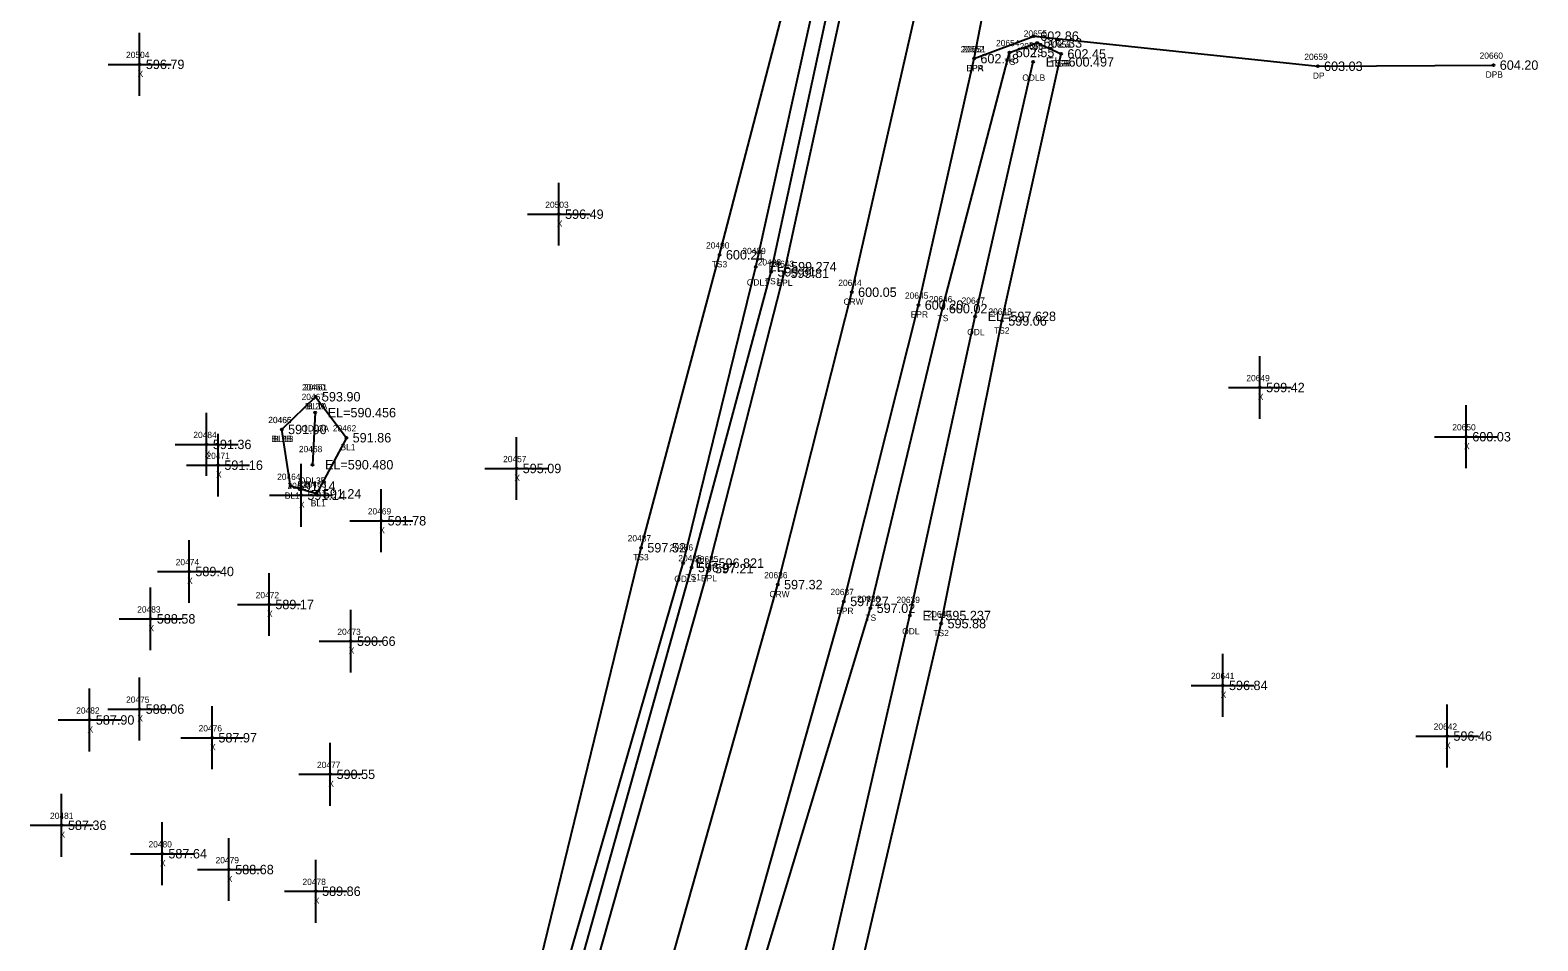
# Model space of a CAD drawing. Extents: x 1695443 to 1696344, y 1087542 to 1090645.
# Drawn here: x 1695668.2 to 1695908, y 1089671.2 to 1089816.1 of the extents above; entities that cross this region are included whole.
import ezdxf

# ---------------------------------------------------------------- set-up
doc = ezdxf.new("R2010")
doc.units = 0
for name, color, linetype in [('RD_DTM_BkLn1', 7, 'Continuous'), ('RD_DTM_BkLn2', 7, 'Continuous'), ('RD_DTM_BkLn_txCode', 7, 'Continuous'), ('RD_EX_Driveway', 7, 'Continuous'), ('RD_EX_Driveway_txCode', 7, 'Continuous'), ('RD_EX_H2O', 7, 'Continuous'), ('RD_EX_H2O_txCode', 7, 'Continuous'), ('RD_EX_Misc', 7, 'Continuous'), ('RD_EX_Misc_txCode', 7, 'Continuous'), ('RD_EX_Road', 7, 'Continuous'), ('RD_EX_Road_txCode', 7, 'Continuous'), ('RD_EX_TX_Driveway_ELEV', 7, 'Continuous'), ('RD_EX_TX_H2O_ELEV', 7, 'Continuous'), ('RD_EX_TX_Misc_ELEV', 7, 'Continuous'), ('RD_EX_TX_Road_ELEV', 7, 'Continuous'), ('RD_HC_Survey_ELEV', 7, 'Continuous'), ('RD_HC_Survey_txCode', 7, 'Continuous'), ('RD_SMD_Locator', 7, 'Continuous')]:
    doc.layers.add(name, color=color, linetype=linetype)

msp = doc.modelspace()

# ---------------------------------------------------------------- linework, layer by layer
at = {"layer": 'RD_DTM_BkLn1'}
msp.add_line((1695713.6, 1089757.78), (1695708.22, 1089752.58), dxfattribs=at)
for points in [[(1695813.78, 1089148.1), (1695785.55, 1089189.03), (1695758.89, 1089235.87), (1695740.64, 1089279.02), (1695725.17, 1089334.02), (1695718.27, 1089382.65), (1695717.41, 1089435.13), (1695722.03, 1089482.62), (1695732.64, 1089534.75), (1695759.85, 1089631.43), (1695787.11, 1089727.89), (1695798.89, 1089774.41), (1695810.31, 1089824.5), (1695818.49, 1089870.61), (1695825.85, 1089922.33), (1695831.69, 1089976.57), (1695835.49, 1090019.27), (1695844.06, 1090117.91), (1695852.56, 1090215.73), (1695861.78, 1090313.02), (1695870.8, 1090411.68), (1695879.44, 1090510.15), (1695888.04, 1090606.94)], [(1695713.6, 1089757.78), (1695718.49, 1089751.26), (1695713.75, 1089742.33), (1695709.63, 1089743.55), (1695708.22, 1089752.58)]]:
    msp.add_lwpolyline(points, dxfattribs=at)
at = {"layer": 'RD_DTM_BkLn2'}
for points in [[(1695696.87, 1089328.65), (1695685.13, 1089358.98), (1695692.41, 1089382.13), (1695691.76, 1089435.56), (1695699.73, 1089488.72), (1695712.17, 1089543.62), (1695742.06, 1089638.06), (1695765.36, 1089733.76), (1695777.86, 1089780.36), (1695790.39, 1089828.61), (1695799.49, 1089874.59), (1695809.45, 1089923.14)], [(1695802.49, 1089139.56), (1695797.31, 1089139.87), (1695796.55, 1089145.92), (1695767.85, 1089172.77), (1695752.08, 1089198.99), (1695743.04, 1089224.25), (1695723.93, 1089271.63), (1695706.46, 1089330), (1695701.78, 1089380.95), (1695703.12, 1089435.75), (1695708.88, 1089486.48), (1695720.72, 1089539.1), (1695747.1, 1089636.56), (1695773.41, 1089730.59), (1695786.04, 1089777.66), (1695796.55, 1089826.24), (1695804.53, 1089873.75), (1695809.45, 1089923.14)], [(1695824.1, 1089156.08), (1695822.08, 1089163.12), (1695799.61, 1089199.21), (1695776.92, 1089245.16), (1695754.8, 1089284.38), (1695737.73, 1089336.15), (1695730.34, 1089383.59), (1695730.57, 1089435.13), (1695734.2, 1089480.03), (1695745.77, 1089531.16), (1695772.55, 1089627.13), (1695801.84, 1089724.13), (1695813.32, 1089771.8), (1695823.97, 1089812.55), (1695828.38, 1089814.06), (1695832.18, 1089812.32)], [(1695733.01, 1089422.34), (1695739.17, 1089435.08), (1695740.22, 1089478.28), (1695758.62, 1089527.7), (1695775.29, 1089579.66), (1695790.54, 1089625.04), (1695813.11, 1089721.69), (1695822.77, 1089769.83), (1695832.18, 1089812.32)]]:
    msp.add_lwpolyline(points, dxfattribs=at)
at = {"layer": 'RD_EX_Driveway'}
msp.add_lwpolyline([(1695818.34, 1089811.57), (1695827.86, 1089815.15), (1695873, 1089810.36), (1695900.95, 1089810.54)], dxfattribs=at)
at = {"layer": 'RD_EX_H2O'}
msp.add_line((1695713.52, 1089755.25), (1695713.09, 1089746.96), dxfattribs=at)
for points in [[(1695696.87, 1089328.65), (1695699.57, 1089380.43), (1695700.06, 1089435.96), (1695707.01, 1089487.43), (1695718.96, 1089539.87), (1695744.93, 1089637.33), (1695772.06, 1089731.31), (1695783.6, 1089778.47), (1695794.38, 1089827.05), (1695802.7, 1089874.04), (1695809.45, 1089923.14)], [(1695733.01, 1089422.34), (1695733.36, 1089435.29), (1695736.08, 1089479.97), (1695750.56, 1089529.82), (1695767.47, 1089581.7), (1695784.92, 1089622.19), (1695808.14, 1089722.97), (1695818.49, 1089770.57), (1695827.73, 1089811.05)]]:
    msp.add_lwpolyline(points, dxfattribs=at)
at = {"layer": 'RD_EX_Misc'}
for p, q in [((1695685.6, 1089805.66), (1695685.6, 1089815.66)), ((1695680.6, 1089810.66), (1695690.6, 1089810.66)), ((1695752.28, 1089781.82), (1695752.28, 1089791.82)), ((1695747.28, 1089786.82), (1695757.28, 1089786.82)), ((1695863.79, 1089754.25), (1695863.79, 1089764.25)), ((1695858.79, 1089759.25), (1695868.79, 1089759.25)), ((1695696.26, 1089745.2), (1695696.26, 1089755.2)), ((1695896.58, 1089746.42), (1695896.58, 1089756.42)), ((1695691.26, 1089750.2), (1695701.26, 1089750.2)), ((1695698.08, 1089741.89), (1695698.08, 1089751.89)), ((1695745.54, 1089741.37), (1695745.54, 1089751.37)), ((1695891.58, 1089751.42), (1695901.58, 1089751.42)), ((1695711.28, 1089737.11), (1695711.28, 1089747.11)), ((1695693.08, 1089746.89), (1695703.08, 1089746.89)), ((1695740.54, 1089746.37), (1695750.54, 1089746.37)), ((1695724.05, 1089733.05), (1695724.05, 1089743.05)), ((1695706.28, 1089742.11), (1695716.28, 1089742.11)), ((1695719.05, 1089738.05), (1695729.05, 1089738.05)), ((1695693.47, 1089724.98), (1695693.47, 1089734.98)), ((1695688.47, 1089729.98), (1695698.47, 1089729.98)), ((1695706.19, 1089719.73), (1695706.19, 1089729.73)), ((1695687.34, 1089717.44), (1695687.34, 1089727.44)), ((1695701.19, 1089724.73), (1695711.19, 1089724.73)), ((1695719.18, 1089713.89), (1695719.18, 1089723.89)), ((1695682.34, 1089722.44), (1695692.34, 1089722.44)), ((1695714.18, 1089718.89), (1695724.18, 1089718.89)), ((1695857.88, 1089706.86), (1695857.88, 1089716.86)), ((1695677.64, 1089701.36), (1695677.64, 1089711.36)), ((1695685.57, 1089703.09), (1695685.57, 1089713.09)), ((1695852.88, 1089711.86), (1695862.88, 1089711.86)), ((1695893.58, 1089698.8), (1695893.58, 1089708.8)), ((1695672.64, 1089706.36), (1695682.64, 1089706.36)), ((1695680.57, 1089708.09), (1695690.57, 1089708.09)), ((1695697.14, 1089698.53), (1695697.14, 1089708.53)), ((1695692.14, 1089703.53), (1695702.14, 1089703.53)), ((1695715.93, 1089692.71), (1695715.93, 1089702.71)), ((1695888.58, 1089703.8), (1695898.58, 1089703.8)), ((1695710.93, 1089697.71), (1695720.93, 1089697.71)), ((1695673.2, 1089684.61), (1695673.2, 1089694.61)), ((1695668.2, 1089689.61), (1695678.2, 1089689.61)), ((1695689.18, 1089680.08), (1695689.18, 1089690.08)), ((1695699.81, 1089677.56), (1695699.81, 1089687.56)), ((1695684.18, 1089685.08), (1695694.18, 1089685.08)), ((1695694.81, 1089682.56), (1695704.81, 1089682.56)), ((1695713.63, 1089674.11), (1695713.63, 1089684.11)), ((1695708.63, 1089679.11), (1695718.63, 1089679.11))]:
    msp.add_line(p, q, dxfattribs=at)
at = {"layer": 'RD_EX_Road'}
for points in [[(1695813.78, 1089148.1), (1695805.56, 1089142.08), (1695776.44, 1089183.94), (1695749.27, 1089231.88), (1695730.49, 1089275.72), (1695714.87, 1089332.12), (1695707.87, 1089381.72), (1695706.58, 1089435.34), (1695711.58, 1089484.26), (1695722.15, 1089537.59), (1695749.04, 1089634.88), (1695776.11, 1089730.43), (1695788.13, 1089777.42), (1695798.89, 1089826.76), (1695807.1, 1089870.03), (1695814.71, 1089923.3), (1695820.51, 1089978.16), (1695824.04, 1090019.79), (1695832.76, 1090119.06), (1695841.25, 1090216.76), (1695850.36, 1090314.41), (1695859.24, 1090411.82), (1695868.09, 1090511.63), (1695876.75, 1090608.38)], [(1695728.69, 1089383.6), (1695727.9, 1089434.83), (1695732.68, 1089480.1), (1695743.4, 1089531.84), (1695770.35, 1089628.36), (1695797.63, 1089725.22), (1695809.49, 1089772.37), (1695818.34, 1089811.57), (1695820.65, 1089823.41), (1695822.99, 1089835.26), (1695829.18, 1089869.37), (1695836.32, 1089920.97), (1695842.44, 1089975.46), (1695846.49, 1090018.55), (1695849.32, 1090055.39), (1695850.91, 1090072.92), (1695855.09, 1090117.49), (1695863.53, 1090214.93), (1695872.56, 1090312.44), (1695881.69, 1090410.78), (1695890.45, 1090509.3), (1695899.01, 1090605.4)]]:
    msp.add_lwpolyline(points, dxfattribs=at)
at = {"layer": 'RD_SMD_Locator'}
for centre in [(1695827.86, 1089815.15), (1695823.97, 1089812.55), (1695828.38, 1089814.06), (1695832.18, 1089812.32), (1695832.18, 1089812.32), (1695685.6, 1089810.66), (1695818.34, 1089811.57), (1695818.34, 1089811.57), (1695827.73, 1089811.05), (1695873, 1089810.36), (1695900.95, 1089810.54), (1695752.28, 1089786.82), (1695777.86, 1089780.36), (1695783.6, 1089778.47), (1695786.04, 1089777.66), (1695788.13, 1089777.42), (1695798.89, 1089774.41), (1695809.49, 1089772.37), (1695813.32, 1089771.8), (1695818.49, 1089770.57), (1695822.77, 1089769.83), (1695863.79, 1089759.25), (1695713.6, 1089757.78), (1695713.6, 1089757.78), (1695713.52, 1089755.25), (1695708.22, 1089752.58), (1695708.22, 1089752.58), (1695696.26, 1089750.2), (1695718.49, 1089751.26), (1695896.58, 1089751.42), (1695713.09, 1089746.96), (1695698.08, 1089746.89), (1695745.54, 1089746.37), (1695709.63, 1089743.55), (1695713.75, 1089742.33), (1695711.28, 1089742.11), (1695724.05, 1089738.05), (1695765.36, 1089733.76), (1695772.06, 1089731.31), (1695773.41, 1089730.59), (1695776.11, 1089730.43), (1695693.47, 1089729.98), (1695787.11, 1089727.89), (1695706.19, 1089724.73), (1695797.63, 1089725.22), (1695801.84, 1089724.13), (1695808.14, 1089722.97), (1695687.34, 1089722.44), (1695813.11, 1089721.69), (1695719.18, 1089718.89), (1695857.88, 1089711.86), (1695677.64, 1089706.36), (1695685.57, 1089708.09), (1695893.58, 1089703.8), (1695697.14, 1089703.53), (1695715.93, 1089697.71), (1695673.2, 1089689.61), (1695689.18, 1089685.08), (1695699.81, 1089682.56), (1695713.63, 1089679.11)]:
    msp.add_circle(centre, 0.15, dxfattribs=at)

# ---------------------------------------------------------------- texts
at = {"layer": 'RD_DTM_BkLn_txCode'}
for s, p in [('20654', (1695821.83, 1089813.55)), ('20655', (1695826.23, 1089815.06)), ('20656', (1695830.01, 1089813.32)), ('20657', (1695830.04, 1089813.32)), ('TS', (1695827.58, 1089812.06)), ('TS', (1695823.18, 1089810.55)), ('TS2B', (1695830.46, 1089810.32)), ('TSB', (1695830.91, 1089810.32)), ('20490', (1695775.7, 1089781.36)), ('TS3', (1695776.61, 1089778.36)), ('20488', (1695783.92, 1089778.66)), ('TS1', (1695785.08, 1089775.66)), ('20646', (1695811.16, 1089772.8)), ('20648', (1695820.62, 1089770.83)), ('TS', (1695812.53, 1089769.8)), ('TS2', (1695821.52, 1089767.83)), ('20460', (1695711.42, 1089758.78)), ('20461', (1695711.74, 1089758.78)), ('BL2A', (1695711.91, 1089755.78)), ('BL1A', (1695712.19, 1089755.78)), ('20466', (1695706.05, 1089753.58)), ('20465', (1695706.08, 1089753.58)), ('20462', (1695716.34, 1089752.26)), ('BL2B', (1695706.54, 1089750.58)), ('BL1B', (1695706.83, 1089750.58)), ('BL1', (1695717.56, 1089749.26)), ('20464', (1695707.48, 1089744.55)), ('BL1', (1695708.7, 1089741.55)), ('20463', (1695711.61, 1089743.33)), ('BL1', (1695712.83, 1089740.33)), ('20487', (1695763.24, 1089734.76)), ('TS3', (1695764.12, 1089731.76)), ('20485', (1695771.29, 1089731.59)), ('TS1', (1695772.44, 1089728.59)), ('20638', (1695799.7, 1089725.13)), ('TS', (1695801.05, 1089722.13)), ('20640', (1695810.93, 1089722.69)), ('TS2', (1695811.87, 1089719.69))]:
    msp.add_text(s, height=1, dxfattribs=at).set_placement(p)
at = {"layer": 'RD_EX_Driveway_txCode'}
for s, p in [('20652', (1695816.2, 1089812.57)), ('DP', (1695827.08, 1089813.15)), ('20659', (1695870.86, 1089811.36)), ('20660', (1695898.74, 1089811.54)), ('DPA', (1695817.08, 1089809.57)), ('DPB', (1695899.7, 1089808.54)), ('DP', (1695872.22, 1089808.36))]:
    msp.add_text(s, height=1, dxfattribs=at).set_placement(p)
at = {"layer": 'RD_EX_H2O_txCode'}
for s, p in [('20658', (1695825.58, 1089813.05)), ('ODLB', (1695826.01, 1089808.05)), ('20489', (1695781.48, 1089780.47)), ('ODL1', (1695782.19, 1089775.47)), ('20647', (1695816.35, 1089772.57)), ('ODL', (1695817.24, 1089767.57)), ('20467', (1695711.37, 1089757.25)), ('ODL3A', (1695711.33, 1089752.25)), ('20468', (1695710.94, 1089748.96)), ('ODL3B', (1695710.92, 1089743.96)), ('20486', (1695769.92, 1089733.31)), ('ODL1', (1695770.65, 1089728.31)), ('20639', (1695806, 1089724.97)), ('ODL', (1695806.9, 1089719.97))]:
    msp.add_text(s, height=1, dxfattribs=at).set_placement(p)
at = {"layer": 'RD_EX_Misc_txCode'}
for s, p in [('20504', (1695683.45, 1089811.66)), ('X', (1695685.29, 1089808.66)), ('20503', (1695750.13, 1089787.82)), ('X', (1695751.97, 1089784.82)), ('20649', (1695861.64, 1089760.25)), ('X', (1695863.47, 1089757.25)), ('20484', (1695694.15, 1089751.2)), ('20650', (1695894.4, 1089752.42)), ('X', (1695896.27, 1089749.42)), ('X', (1695695.95, 1089748.2)), ('20471', (1695696.24, 1089747.89)), ('20457', (1695743.42, 1089747.37)), ('X', (1695697.76, 1089744.89)), ('X', (1695745.22, 1089744.37)), ('20470', (1695709.12, 1089743.11)), ('X', (1695710.97, 1089740.11)), ('20469', (1695721.9, 1089739.05)), ('X', (1695723.73, 1089736.05)), ('20474', (1695691.35, 1089730.98)), ('X', (1695693.16, 1089727.98)), ('20472', (1695704.07, 1089725.73)), ('20483', (1695685.22, 1089723.44)), ('X', (1695705.88, 1089722.73)), ('X', (1695687.02, 1089720.44)), ('20473', (1695717.06, 1089719.89)), ('X', (1695718.87, 1089716.89)), ('20641', (1695856.02, 1089712.86)), ('20475', (1695683.45, 1089709.09)), ('X', (1695857.56, 1089709.86)), ('20482', (1695675.52, 1089707.36)), ('X', (1695685.25, 1089706.09)), ('X', (1695677.33, 1089704.36)), ('20476', (1695694.99, 1089704.53)), ('20642', (1695891.44, 1089704.8)), ('X', (1695696.82, 1089701.53)), ('X', (1695893.26, 1089701.8)), ('20477', (1695713.82, 1089698.71)), ('X', (1695715.62, 1089695.71)), ('20481', (1695671.36, 1089690.61)), ('X', (1695672.88, 1089687.61)), ('20480', (1695687.02, 1089686.08)), ('X', (1695688.86, 1089683.08)), ('20479', (1695697.69, 1089683.56)), ('X', (1695699.49, 1089680.56)), ('20478', (1695711.51, 1089680.11)), ('X', (1695713.32, 1089677.11))]:
    msp.add_text(s, height=1, dxfattribs=at).set_placement(p)
at = {"layer": 'RD_EX_Road_txCode'}
for s, p in [('20651', (1695816.48, 1089812.57)), ('EPR', (1695817.11, 1089809.57)), ('20643', (1695785.99, 1089778.42)), ('EPL', (1695786.92, 1089775.42)), ('20645', (1695807.34, 1089773.37)), ('EPR', (1695808.26, 1089770.37)), ('20635', (1695773.96, 1089731.43)), ('EPL', (1695774.9, 1089728.43)), ('20637', (1695795.49, 1089726.22)), ('EPR', (1695796.41, 1089723.22))]:
    msp.add_text(s, height=1, dxfattribs=at).set_placement(p)
at = {"layer": 'RD_EX_TX_Driveway_ELEV'}
for s, p in [('602.86', (1695828.86, 1089814.4)), ('602.48', (1695819.34, 1089810.82)), ('603.03', (1695874, 1089809.61)), ('604.20', (1695901.95, 1089809.79))]:
    msp.add_text(s, height=1.5, dxfattribs=at).set_placement(p)
at = {"layer": 'RD_EX_TX_H2O_ELEV'}
for s, p in [('EL=600.497', (1695829.73, 1089810.3)), ('EL=599.274', (1695785.6, 1089777.72)), ('EL=597.628', (1695820.49, 1089769.82)), ('EL=590.456', (1695715.52, 1089754.5)), ('EL=590.480', (1695715.09, 1089746.21)), ('EL=596.821', (1695774.06, 1089730.56)), ('EL=595.237', (1695810.14, 1089722.22))]:
    msp.add_text(s, height=1.5, dxfattribs=at).set_placement(p)
at = {"layer": 'RD_EX_TX_Misc_ELEV'}
for s, p in [('602.33', (1695829.38, 1089813.31)), ('602.55', (1695824.97, 1089811.8)), ('602.45', (1695833.18, 1089811.57)), ('602.45', (1695833.18, 1089811.57)), ('596.79', (1695686.6, 1089809.91)), ('596.49', (1695753.28, 1089786.07)), ('600.21', (1695778.86, 1089779.61)), ('599.61', (1695787.04, 1089776.91)), ('600.02', (1695814.32, 1089771.05)), ('599.06', (1695823.77, 1089769.08)), ('599.42', (1695864.79, 1089758.5)), ('593.90', (1695714.6, 1089757.03)), ('593.90', (1695714.6, 1089757.03)), ('591.90', (1695709.22, 1089751.83)), ('591.90', (1695709.22, 1089751.83)), ('591.86', (1695719.49, 1089750.51)), ('600.03', (1695897.58, 1089750.67)), ('591.36', (1695697.26, 1089749.45)), ('591.16', (1695699.08, 1089746.14)), ('595.09', (1695746.54, 1089745.62)), ('591.14', (1695710.63, 1089742.8)), ('591.14', (1695712.28, 1089741.36)), ('591.24', (1695714.75, 1089741.58)), ('591.78', (1695725.05, 1089737.3)), ('597.52', (1695766.36, 1089733.01)), ('589.40', (1695694.47, 1089729.23)), ('596.97', (1695774.41, 1089729.84)), ('588.58', (1695688.34, 1089721.69)), ('589.17', (1695707.19, 1089723.98)), ('597.02', (1695802.84, 1089723.38)), ('595.88', (1695814.11, 1089720.94)), ('590.66', (1695720.18, 1089718.14)), ('596.84', (1695858.88, 1089711.11)), ('588.06', (1695686.57, 1089707.34)), ('587.90', (1695678.64, 1089705.61)), ('587.97', (1695698.14, 1089702.78)), ('596.46', (1695894.58, 1089703.05)), ('590.55', (1695716.93, 1089696.96)), ('587.36', (1695674.2, 1089688.86)), ('587.64', (1695690.18, 1089684.33)), ('588.68', (1695700.81, 1089681.81)), ('589.86', (1695714.63, 1089678.36))]:
    msp.add_text(s, height=1.5, dxfattribs=at).set_placement(p)
at = {"layer": 'RD_EX_TX_Road_ELEV'}
for s, p in [('602.48', (1695819.34, 1089810.82)), ('599.81', (1695789.13, 1089776.67)), ('600.20', (1695810.49, 1089771.62)), ('597.21', (1695777.11, 1089729.68)), ('597.27', (1695798.63, 1089724.47))]:
    msp.add_text(s, height=1.5, dxfattribs=at).set_placement(p)
at = {"layer": 'RD_HC_Survey_ELEV'}
for s, p in [('600.05', (1695799.89, 1089773.66)), ('597.32', (1695788.11, 1089727.14))]:
    msp.add_text(s, height=1.5, dxfattribs=at).set_placement(p)
at = {"layer": 'RD_HC_Survey_txCode'}
for s, p in [('20644', (1695796.74, 1089775.41)), ('CRW', (1695797.57, 1089772.41)), ('20636', (1695784.94, 1089728.89)), ('CRW', (1695785.79, 1089725.89))]:
    msp.add_text(s, height=1, dxfattribs=at).set_placement(p)

doc.saveas('drawing.dxf')
